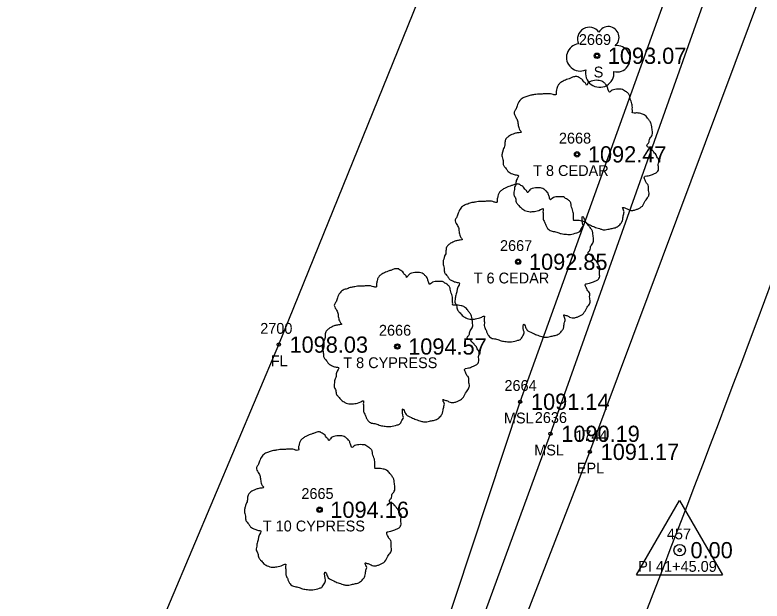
# Model space of a CAD drawing. Extents: x 1578957 to 1581675, y 1115963 to 1120391.
# Drawn here: x 1580656.7 to 1580725.7, y 1119311 to 1119365.2 of the extents above; entities that cross this region are included whole.
import ezdxf

# ---------------------------------------------------------------- set-up
doc = ezdxf.new("R2010")
doc.units = 0
for name, color, linetype in [('RD_EX_Fence_Other', 7, 'Continuous'), ('RD_EX_Fence_Other_txCode', 7, 'Continuous'), ('RD_EX_Misc', 7, 'Continuous'), ('RD_EX_Misc_txCode', 7, 'Continuous'), ('RD_EX_Road', 7, 'Continuous'), ('RD_EX_Road_txCode', 7, 'Continuous'), ('RD_EX_TX_Fence_Other_ELEV', 7, 'Continuous'), ('RD_EX_TX_Misc_ELEV', 7, 'Continuous'), ('RD_EX_TX_Road_ELEV', 7, 'Continuous'), ('RD_EX_TX_VEG_ELEV', 7, 'Continuous'), ('RD_EX_VEG', 7, 'Continuous'), ('RD_EX_VEG_txCode', 7, 'Continuous'), ('RD_HC_Cl', 7, 'Continuous'), ('RD_HC_Data', 7, 'Continuous'), ('RD_HC_Survey_ELEV', 7, 'Continuous'), ('RD_HC_txCode', 7, 'Continuous'), ('RD_SMD_Locator', 7, 'Continuous')]:
    doc.layers.add(name, color=color, linetype=linetype)

msp = doc.modelspace()

# ---------------------------------------------------------------- linework, layer by layer
at = {"layer": 'RD_EX_Fence_Other'}
msp.add_lwpolyline([(1580513.827, 1119078.662), (1580554.331, 1119026.263), (1580554.331, 1119026.263), (1580661.056, 1119287.238), (1580681.048, 1119334.68), (1580698.952, 1119378.888), (1580718.027, 1119424.961), (1580737.744, 1119473.232)], dxfattribs=at)
at = {"layer": 'RD_EX_Misc'}
for points in [[(1580575.469, 1119001.964), (1580572.192, 1119003.299), (1580573.344, 1119008.973), (1580569.078, 1119017.528), (1580583.69, 1119050.381), (1580599.817, 1119098.808), (1580624.045, 1119165.829), (1580641.396, 1119195.473), (1580666.371, 1119238.149), (1580687.021, 1119280.073), (1580703.349, 1119329.398), (1580719.477, 1119374.249), (1580736.36, 1119422.972), (1580751.158, 1119471.49)], [(1580572.228, 1119003.293), (1580577.641, 1119002.275), (1580593.887, 1119048.73), (1580611.465, 1119096.441), (1580629.396, 1119141.91), (1580650.31, 1119188.617), (1580669.532, 1119232.972), (1580689.078, 1119279.767), (1580706.148, 1119326.435), (1580722.862, 1119373.532), (1580740.07, 1119420.2), (1580755.304, 1119467.381)]]:
    msp.add_lwpolyline(points, dxfattribs=at)
at = {"layer": 'RD_EX_Road'}
msp.add_lwpolyline([(1580561.509, 1118902.856), (1580569.284, 1118952.033), (1580572.257, 1118964.729), (1580572.024, 1118971.684), (1580570.785, 1118976.943), (1580576.68, 1118999.159), (1580578.916, 1119000.71), (1580583.17, 1119008.339), (1580597.232, 1119047.928), (1580615.21, 1119094.659), (1580634.106, 1119140.594), (1580653.543, 1119186.411), (1580672.941, 1119232.27), (1580691.817, 1119278.399), (1580709.783, 1119324.767), (1580727.167, 1119371.358), (1580744.517, 1119418.33), (1580760.444, 1119465.683)], dxfattribs=at)
at = {"layer": 'RD_EX_VEG'}
for centre, radius in [((1580710.447, 1119361.381), 0.25), ((1580708.606, 1119352.268), 0.25), ((1580708.593, 1119352.249), 0.0001), ((1580703.165, 1119342.335), 0.25), ((1580703.152, 1119342.316), 0.0001), ((1580692.007, 1119334.506), 0.25), ((1580691.994, 1119334.487), 0.0001), ((1580684.82, 1119319.412), 0.25), ((1580684.807, 1119319.394), 0.0001)]:
    msp.add_circle(centre, radius, dxfattribs=at)
for centre, radius, start, end in [((1580709.726, 1119362.928), 1.084, 34.97629, 204.75602), ((1580711.492, 1119363.083), 0.995, 308.76261, 152.04674), ((1580708.883, 1119361.225), 1.257, 96.45179, 294.73401), ((1580712.287, 1119361.101), 1.218, 256.56668, 98.10463), ((1580710.692, 1119359.784), 1.318, 166.88266, 5.75893)]:
    msp.add_arc(centre, radius, start, end, dxfattribs=at)
for points in [[(1580708.738, 1119359.435), (1580708.438, 1119359.46), (1580708.113, 1119359.36), (1580707.863, 1119359.26), (1580707.638, 1119359.185), (1580707.413, 1119359.085), (1580707.113, 1119358.91), (1580706.888, 1119358.71), (1580706.763, 1119358.461), (1580706.713, 1119358.236), (1580706.663, 1119357.961), (1580706.663, 1119357.786), (1580706.539, 1119357.761), (1580706.389, 1119357.786), (1580706.139, 1119357.861), (1580705.889, 1119357.861), (1580705.639, 1119357.861), (1580705.289, 1119357.836), (1580704.939, 1119357.836), (1580704.664, 1119357.786), (1580704.339, 1119357.736), (1580703.965, 1119357.611), (1580703.615, 1119357.486), (1580703.315, 1119357.236), (1580703.065, 1119356.761), (1580702.94, 1119356.411), (1580702.79, 1119356.162), (1580702.94, 1119355.712), (1580703.115, 1119355.362), (1580703.14, 1119355.162), (1580703.215, 1119354.737), (1580703.315, 1119354.512), (1580703.44, 1119354.312), (1580703.365, 1119354.287), (1580702.99, 1119354.237), (1580702.69, 1119354.137), (1580702.265, 1119353.913), (1580702.04, 1119353.688), (1580701.94, 1119353.363), (1580701.916, 1119353.013), (1580701.816, 1119352.813), (1580701.741, 1119352.538), (1580701.716, 1119352.463), (1580701.666, 1119352.138), (1580701.766, 1119351.688), (1580701.791, 1119351.339), (1580701.916, 1119351.114), (1580702.065, 1119350.939), (1580702.24, 1119350.689), (1580702.64, 1119350.464), (1580702.965, 1119350.364), (1580703.165, 1119350.339), (1580702.99, 1119349.839), (1580702.94, 1119349.489), (1580702.815, 1119349.09), (1580702.815, 1119349.015), (1580702.765, 1119348.54), (1580702.915, 1119348.215), (1580702.99, 1119347.84), (1580703.165, 1119347.615), (1580703.44, 1119347.315), (1580703.765, 1119347.091), (1580704.265, 1119346.966), (1580704.664, 1119346.991), (1580705.239, 1119347.165), (1580705.489, 1119347.24), (1580705.464, 1119347.066), (1580705.489, 1119346.691), (1580705.489, 1119346.266), (1580705.639, 1119345.941), (1580705.739, 1119345.666), (1580705.889, 1119345.416), (1580706.214, 1119345.191), (1580706.613, 1119345.116), (1580707.038, 1119344.966), (1580707.488, 1119344.891), (1580707.988, 1119344.866), (1580708.588, 1119345.016), (1580708.862, 1119345.141), (1580708.962, 1119345.316), (1580709.162, 1119345.691), (1580709.112, 1119345.916), (1580709.137, 1119346.516), (1580709.237, 1119346.341), (1580709.412, 1119345.991), (1580709.912, 1119345.691), (1580710.312, 1119345.516), (1580710.787, 1119345.366), (1580711.087, 1119345.291), (1580711.561, 1119345.366), (1580711.936, 1119345.441), (1580712.311, 1119345.566), (1580712.611, 1119345.841), (1580712.786, 1119346.116), (1580712.836, 1119346.391), (1580712.911, 1119346.766), (1580712.961, 1119346.941)], [(1580712.961, 1119346.941), (1580712.886, 1119347.116), (1580712.836, 1119347.365), (1580712.911, 1119347.34), (1580713.086, 1119347.29), (1580713.361, 1119347.165), (1580713.585, 1119347.091), (1580713.91, 1119347.116), (1580714.185, 1119347.215), (1580714.635, 1119347.49), (1580714.91, 1119347.965), (1580715.185, 1119348.365), (1580715.26, 1119348.69), (1580715.21, 1119348.915), (1580715.185, 1119349.414), (1580714.985, 1119349.664), (1580714.935, 1119349.789), (1580714.835, 1119350.189), (1580714.91, 1119350.239), (1580715.185, 1119350.289), (1580715.56, 1119350.414), (1580715.834, 1119350.539), (1580716.059, 1119350.714), (1580716.134, 1119350.939), (1580716.109, 1119351.339), (1580716.159, 1119351.738), (1580716.084, 1119351.888), (1580715.984, 1119352.038), (1580715.909, 1119352.238), (1580715.759, 1119352.388), (1580715.66, 1119352.538), (1580715.56, 1119352.638), (1580715.435, 1119352.788), (1580715.26, 1119352.913), (1580715.11, 1119352.963), (1580715.06, 1119353.113), (1580715.21, 1119353.313), (1580715.26, 1119353.413), (1580715.285, 1119353.638), (1580715.51, 1119353.987), (1580715.56, 1119354.387), (1580715.51, 1119354.812), (1580715.46, 1119355.087), (1580715.31, 1119355.362), (1580715.11, 1119355.612), (1580714.985, 1119355.787), (1580714.81, 1119355.912), (1580714.485, 1119356.037), (1580714.235, 1119356.087), (1580713.885, 1119356.087), (1580713.685, 1119356.137), (1580713.71, 1119356.187), (1580713.71, 1119356.336), (1580713.71, 1119356.611), (1580713.635, 1119357.061), (1580713.485, 1119357.561), (1580713.485, 1119357.586), (1580713.385, 1119357.836), (1580713.161, 1119358.036), (1580712.986, 1119358.136), (1580712.786, 1119358.261), (1580712.536, 1119358.286), (1580712.236, 1119358.286), (1580711.961, 1119358.236), (1580711.761, 1119358.136), (1580711.586, 1119358.011), (1580711.511, 1119358.161), (1580711.411, 1119358.461), (1580711.361, 1119358.61), (1580711.211, 1119358.785), (1580710.987, 1119358.985), (1580710.537, 1119359.11), (1580709.912, 1119359.035), (1580709.612, 1119358.835), (1580709.462, 1119358.66), (1580709.412, 1119358.785), (1580709.212, 1119358.985), (1580709.112, 1119359.16), (1580708.937, 1119359.285), (1580708.788, 1119359.385), (1580708.688, 1119359.435)], [(1580703.297, 1119349.502), (1580702.997, 1119349.527), (1580702.672, 1119349.427), (1580702.422, 1119349.327), (1580702.197, 1119349.252), (1580701.972, 1119349.152), (1580701.673, 1119348.977), (1580701.448, 1119348.777), (1580701.323, 1119348.527), (1580701.273, 1119348.302), (1580701.223, 1119348.028), (1580701.223, 1119347.853), (1580701.098, 1119347.828), (1580700.948, 1119347.853), (1580700.698, 1119347.928), (1580700.448, 1119347.928), (1580700.198, 1119347.928), (1580699.848, 1119347.903), (1580699.498, 1119347.903), (1580699.224, 1119347.853), (1580698.899, 1119347.803), (1580698.524, 1119347.678), (1580698.174, 1119347.553), (1580697.874, 1119347.303), (1580697.624, 1119346.828), (1580697.499, 1119346.478), (1580697.349, 1119346.228), (1580697.499, 1119345.779), (1580697.674, 1119345.429), (1580697.699, 1119345.229), (1580697.774, 1119344.804), (1580697.874, 1119344.579), (1580697.999, 1119344.379), (1580697.924, 1119344.354), (1580697.549, 1119344.304), (1580697.249, 1119344.204), (1580696.825, 1119343.979), (1580696.6, 1119343.754), (1580696.5, 1119343.429), (1580696.475, 1119343.08), (1580696.375, 1119342.88), (1580696.3, 1119342.605), (1580696.275, 1119342.53), (1580696.225, 1119342.205), (1580696.325, 1119341.755), (1580696.35, 1119341.405), (1580696.475, 1119341.18), (1580696.625, 1119341.006), (1580696.8, 1119340.756), (1580697.199, 1119340.531), (1580697.524, 1119340.431), (1580697.724, 1119340.406), (1580697.549, 1119339.906), (1580697.499, 1119339.556), (1580697.374, 1119339.156), (1580697.374, 1119339.081), (1580697.324, 1119338.607), (1580697.474, 1119338.282), (1580697.549, 1119337.907), (1580697.724, 1119337.682), (1580697.999, 1119337.382), (1580698.324, 1119337.157), (1580698.824, 1119337.032), (1580699.224, 1119337.057), (1580699.798, 1119337.232), (1580700.048, 1119337.307), (1580700.023, 1119337.132), (1580700.048, 1119336.757), (1580700.048, 1119336.333), (1580700.198, 1119336.008), (1580700.298, 1119335.733), (1580700.448, 1119335.483), (1580700.773, 1119335.258), (1580701.173, 1119335.183), (1580701.598, 1119335.033), (1580702.047, 1119334.958), (1580702.547, 1119334.933), (1580703.147, 1119335.083), (1580703.422, 1119335.208), (1580703.522, 1119335.383), (1580703.722, 1119335.758), (1580703.672, 1119335.983), (1580703.697, 1119336.583), (1580703.797, 1119336.408), (1580703.972, 1119336.058), (1580704.471, 1119335.758), (1580704.871, 1119335.583), (1580705.346, 1119335.433), (1580705.646, 1119335.358), (1580706.121, 1119335.433), (1580706.495, 1119335.508), (1580706.87, 1119335.633), (1580707.17, 1119335.908), (1580707.345, 1119336.183), (1580707.395, 1119336.458), (1580707.47, 1119336.832), (1580707.52, 1119337.007)], [(1580707.52, 1119337.007), (1580707.445, 1119337.182), (1580707.395, 1119337.432), (1580707.47, 1119337.407), (1580707.645, 1119337.357), (1580707.92, 1119337.232), (1580708.145, 1119337.157), (1580708.47, 1119337.182), (1580708.744, 1119337.282), (1580709.194, 1119337.557), (1580709.469, 1119338.032), (1580709.744, 1119338.432), (1580709.819, 1119338.757), (1580709.769, 1119338.981), (1580709.744, 1119339.481), (1580709.544, 1119339.731), (1580709.494, 1119339.856), (1580709.394, 1119340.256), (1580709.469, 1119340.306), (1580709.744, 1119340.356), (1580710.119, 1119340.481), (1580710.394, 1119340.606), (1580710.619, 1119340.781), (1580710.694, 1119341.006), (1580710.669, 1119341.405), (1580710.719, 1119341.805), (1580710.644, 1119341.955), (1580710.544, 1119342.105), (1580710.469, 1119342.305), (1580710.319, 1119342.455), (1580710.219, 1119342.605), (1580710.119, 1119342.705), (1580709.994, 1119342.855), (1580709.819, 1119342.98), (1580709.669, 1119343.03), (1580709.619, 1119343.18), (1580709.769, 1119343.38), (1580709.819, 1119343.479), (1580709.844, 1119343.704), (1580710.069, 1119344.054), (1580710.119, 1119344.454), (1580710.069, 1119344.879), (1580710.019, 1119345.154), (1580709.869, 1119345.429), (1580709.669, 1119345.679), (1580709.544, 1119345.853), (1580709.369, 1119345.978), (1580709.044, 1119346.103), (1580708.794, 1119346.153), (1580708.445, 1119346.153), (1580708.245, 1119346.203), (1580708.27, 1119346.253), (1580708.27, 1119346.403), (1580708.27, 1119346.678), (1580708.195, 1119347.128), (1580708.045, 1119347.628), (1580708.045, 1119347.653), (1580707.945, 1119347.903), (1580707.72, 1119348.102), (1580707.545, 1119348.202), (1580707.345, 1119348.327), (1580707.095, 1119348.352), (1580706.795, 1119348.352), (1580706.52, 1119348.302), (1580706.32, 1119348.202), (1580706.146, 1119348.077), (1580706.071, 1119348.227), (1580705.971, 1119348.527), (1580705.921, 1119348.677), (1580705.771, 1119348.852), (1580705.546, 1119349.052), (1580705.096, 1119349.177), (1580704.471, 1119349.102), (1580704.171, 1119348.902), (1580704.021, 1119348.727), (1580703.972, 1119348.852), (1580703.772, 1119349.052), (1580703.672, 1119349.227), (1580703.497, 1119349.352), (1580703.347, 1119349.452), (1580703.247, 1119349.502)], [(1580692.139, 1119341.673), (1580691.839, 1119341.698), (1580691.514, 1119341.598), (1580691.264, 1119341.498), (1580691.039, 1119341.423), (1580690.814, 1119341.323), (1580690.514, 1119341.149), (1580690.29, 1119340.949), (1580690.165, 1119340.699), (1580690.115, 1119340.474), (1580690.065, 1119340.199), (1580690.065, 1119340.024), (1580689.94, 1119339.999), (1580689.79, 1119340.024), (1580689.54, 1119340.099), (1580689.29, 1119340.099), (1580689.04, 1119340.099), (1580688.69, 1119340.074), (1580688.34, 1119340.074), (1580688.066, 1119340.024), (1580687.741, 1119339.974), (1580687.366, 1119339.849), (1580687.016, 1119339.724), (1580686.716, 1119339.474), (1580686.466, 1119339), (1580686.341, 1119338.65), (1580686.191, 1119338.4), (1580686.341, 1119337.95), (1580686.516, 1119337.6), (1580686.541, 1119337.4), (1580686.616, 1119336.975), (1580686.716, 1119336.751), (1580686.841, 1119336.551), (1580686.766, 1119336.526), (1580686.391, 1119336.476), (1580686.091, 1119336.376), (1580685.667, 1119336.151), (1580685.442, 1119335.926), (1580685.342, 1119335.601), (1580685.317, 1119335.251), (1580685.217, 1119335.051), (1580685.142, 1119334.776), (1580685.117, 1119334.701), (1580685.067, 1119334.377), (1580685.167, 1119333.927), (1580685.192, 1119333.577), (1580685.317, 1119333.352), (1580685.467, 1119333.177), (1580685.642, 1119332.927), (1580686.041, 1119332.702), (1580686.366, 1119332.602), (1580686.566, 1119332.577), (1580686.391, 1119332.078), (1580686.341, 1119331.728), (1580686.216, 1119331.328), (1580686.216, 1119331.253), (1580686.166, 1119330.778), (1580686.316, 1119330.453), (1580686.391, 1119330.078), (1580686.566, 1119329.854), (1580686.841, 1119329.554), (1580687.166, 1119329.329), (1580687.666, 1119329.204), (1580688.066, 1119329.229), (1580688.64, 1119329.404), (1580688.89, 1119329.479), (1580688.865, 1119329.304), (1580688.89, 1119328.929), (1580688.89, 1119328.504), (1580689.04, 1119328.179), (1580689.14, 1119327.904), (1580689.29, 1119327.654), (1580689.615, 1119327.43), (1580690.015, 1119327.355), (1580690.439, 1119327.205), (1580690.889, 1119327.13), (1580691.389, 1119327.105), (1580691.989, 1119327.255), (1580692.264, 1119327.38), (1580692.364, 1119327.555), (1580692.564, 1119327.929), (1580692.514, 1119328.154), (1580692.539, 1119328.754), (1580692.638, 1119328.579), (1580692.813, 1119328.229), (1580693.313, 1119327.929), (1580693.713, 1119327.754), (1580694.188, 1119327.604), (1580694.488, 1119327.53), (1580694.962, 1119327.604), (1580695.337, 1119327.679), (1580695.712, 1119327.804), (1580696.012, 1119328.079), (1580696.187, 1119328.354), (1580696.237, 1119328.629), (1580696.312, 1119329.004), (1580696.362, 1119329.179)], [(1580696.362, 1119329.179), (1580696.287, 1119329.354), (1580696.237, 1119329.604), (1580696.312, 1119329.579), (1580696.487, 1119329.529), (1580696.762, 1119329.404), (1580696.987, 1119329.329), (1580697.311, 1119329.354), (1580697.586, 1119329.454), (1580698.036, 1119329.729), (1580698.311, 1119330.203), (1580698.586, 1119330.603), (1580698.661, 1119330.928), (1580698.611, 1119331.153), (1580698.586, 1119331.653), (1580698.386, 1119331.903), (1580698.336, 1119332.028), (1580698.236, 1119332.427), (1580698.311, 1119332.477), (1580698.586, 1119332.527), (1580698.961, 1119332.652), (1580699.236, 1119332.777), (1580699.461, 1119332.952), (1580699.535, 1119333.177), (1580699.511, 1119333.577), (1580699.56, 1119333.977), (1580699.486, 1119334.127), (1580699.386, 1119334.277), (1580699.311, 1119334.477), (1580699.161, 1119334.626), (1580699.061, 1119334.776), (1580698.961, 1119334.876), (1580698.836, 1119335.026), (1580698.661, 1119335.151), (1580698.511, 1119335.201), (1580698.461, 1119335.351), (1580698.611, 1119335.551), (1580698.661, 1119335.651), (1580698.686, 1119335.876), (1580698.911, 1119336.226), (1580698.961, 1119336.626), (1580698.911, 1119337.05), (1580698.861, 1119337.325), (1580698.711, 1119337.6), (1580698.511, 1119337.85), (1580698.386, 1119338.025), (1580698.211, 1119338.15), (1580697.886, 1119338.275), (1580697.636, 1119338.325), (1580697.286, 1119338.325), (1580697.087, 1119338.375), (1580697.112, 1119338.425), (1580697.112, 1119338.575), (1580697.112, 1119338.85), (1580697.037, 1119339.299), (1580696.887, 1119339.799), (1580696.887, 1119339.824), (1580696.787, 1119340.074), (1580696.562, 1119340.274), (1580696.387, 1119340.374), (1580696.187, 1119340.499), (1580695.937, 1119340.524), (1580695.637, 1119340.524), (1580695.362, 1119340.474), (1580695.162, 1119340.374), (1580694.987, 1119340.249), (1580694.912, 1119340.399), (1580694.813, 1119340.699), (1580694.763, 1119340.849), (1580694.613, 1119341.024), (1580694.388, 1119341.224), (1580693.938, 1119341.348), (1580693.313, 1119341.274), (1580693.013, 1119341.074), (1580692.863, 1119340.899), (1580692.813, 1119341.024), (1580692.613, 1119341.224), (1580692.514, 1119341.398), (1580692.339, 1119341.523), (1580692.189, 1119341.623), (1580692.089, 1119341.673)], [(1580684.952, 1119326.58), (1580684.652, 1119326.605), (1580684.327, 1119326.505), (1580684.077, 1119326.405), (1580683.852, 1119326.33), (1580683.627, 1119326.23), (1580683.327, 1119326.055), (1580683.102, 1119325.855), (1580682.977, 1119325.605), (1580682.927, 1119325.38), (1580682.877, 1119325.105), (1580682.877, 1119324.93), (1580682.753, 1119324.905), (1580682.603, 1119324.93), (1580682.353, 1119325.005), (1580682.103, 1119325.005), (1580681.853, 1119325.005), (1580681.503, 1119324.98), (1580681.153, 1119324.98), (1580680.878, 1119324.93), (1580680.553, 1119324.88), (1580680.179, 1119324.755), (1580679.829, 1119324.63), (1580679.529, 1119324.381), (1580679.279, 1119323.906), (1580679.154, 1119323.556), (1580679.004, 1119323.306), (1580679.154, 1119322.856), (1580679.329, 1119322.506), (1580679.354, 1119322.306), (1580679.429, 1119321.882), (1580679.529, 1119321.657), (1580679.654, 1119321.457), (1580679.579, 1119321.432), (1580679.204, 1119321.382), (1580678.904, 1119321.282), (1580678.479, 1119321.057), (1580678.254, 1119320.832), (1580678.154, 1119320.507), (1580678.13, 1119320.157), (1580678.03, 1119319.958), (1580677.955, 1119319.683), (1580677.93, 1119319.608), (1580677.88, 1119319.283), (1580677.98, 1119318.833), (1580678.005, 1119318.483), (1580678.13, 1119318.258), (1580678.279, 1119318.083), (1580678.454, 1119317.833), (1580678.854, 1119317.609), (1580679.179, 1119317.509), (1580679.379, 1119317.484), (1580679.204, 1119316.984), (1580679.154, 1119316.634), (1580679.029, 1119316.234), (1580679.029, 1119316.159), (1580678.979, 1119315.684), (1580679.129, 1119315.359), (1580679.204, 1119314.985), (1580679.379, 1119314.76), (1580679.654, 1119314.46), (1580679.979, 1119314.235), (1580680.479, 1119314.11), (1580680.878, 1119314.135), (1580681.453, 1119314.31), (1580681.703, 1119314.385), (1580681.678, 1119314.21), (1580681.703, 1119313.835), (1580681.703, 1119313.41), (1580681.853, 1119313.086), (1580681.953, 1119312.811), (1580682.103, 1119312.561), (1580682.428, 1119312.336), (1580682.827, 1119312.261), (1580683.252, 1119312.111), (1580683.702, 1119312.036), (1580684.202, 1119312.011), (1580684.802, 1119312.161), (1580685.076, 1119312.286), (1580685.176, 1119312.461), (1580685.376, 1119312.836), (1580685.326, 1119313.061), (1580685.351, 1119313.66), (1580685.451, 1119313.485), (1580685.626, 1119313.135), (1580686.126, 1119312.836), (1580686.526, 1119312.661), (1580687.001, 1119312.511), (1580687.301, 1119312.436), (1580687.775, 1119312.511), (1580688.15, 1119312.586), (1580688.525, 1119312.711), (1580688.825, 1119312.986), (1580689, 1119313.26), (1580689.05, 1119313.535), (1580689.125, 1119313.91), (1580689.175, 1119314.085)], [(1580689.175, 1119314.085), (1580689.1, 1119314.26), (1580689.05, 1119314.51), (1580689.125, 1119314.485), (1580689.3, 1119314.435), (1580689.575, 1119314.31), (1580689.799, 1119314.235), (1580690.124, 1119314.26), (1580690.399, 1119314.36), (1580690.849, 1119314.635), (1580691.124, 1119315.11), (1580691.399, 1119315.509), (1580691.474, 1119315.834), (1580691.424, 1119316.059), (1580691.399, 1119316.559), (1580691.199, 1119316.809), (1580691.149, 1119316.934), (1580691.049, 1119317.334), (1580691.124, 1119317.384), (1580691.399, 1119317.434), (1580691.774, 1119317.559), (1580692.048, 1119317.683), (1580692.273, 1119317.858), (1580692.348, 1119318.083), (1580692.323, 1119318.483), (1580692.373, 1119318.883), (1580692.298, 1119319.033), (1580692.198, 1119319.183), (1580692.123, 1119319.383), (1580691.973, 1119319.533), (1580691.874, 1119319.683), (1580691.774, 1119319.783), (1580691.649, 1119319.933), (1580691.474, 1119320.057), (1580691.324, 1119320.107), (1580691.274, 1119320.257), (1580691.424, 1119320.457), (1580691.474, 1119320.557), (1580691.499, 1119320.782), (1580691.724, 1119321.132), (1580691.774, 1119321.532), (1580691.724, 1119321.957), (1580691.674, 1119322.232), (1580691.524, 1119322.506), (1580691.324, 1119322.756), (1580691.199, 1119322.931), (1580691.024, 1119323.056), (1580690.699, 1119323.181), (1580690.449, 1119323.231), (1580690.099, 1119323.231), (1580689.899, 1119323.281), (1580689.924, 1119323.331), (1580689.924, 1119323.481), (1580689.924, 1119323.756), (1580689.849, 1119324.206), (1580689.699, 1119324.705), (1580689.699, 1119324.73), (1580689.599, 1119324.98), (1580689.375, 1119325.18), (1580689.2, 1119325.28), (1580689, 1119325.405), (1580688.75, 1119325.43), (1580688.45, 1119325.43), (1580688.175, 1119325.38), (1580687.975, 1119325.28), (1580687.8, 1119325.155), (1580687.725, 1119325.305), (1580687.625, 1119325.605), (1580687.575, 1119325.755), (1580687.425, 1119325.93), (1580687.201, 1119326.13), (1580686.751, 1119326.255), (1580686.126, 1119326.18), (1580685.826, 1119325.98), (1580685.676, 1119325.805), (1580685.626, 1119325.93), (1580685.426, 1119326.13), (1580685.326, 1119326.305), (1580685.151, 1119326.43), (1580685.002, 1119326.53), (1580684.902, 1119326.58)]]:
    msp.add_spline(points, degree=3, dxfattribs=at)
at = {"layer": 'RD_HC_Cl'}
msp.add_arc((1578340.815, 1120231.591), 2546.774, 337.467285, 340.391325, dxfattribs=at)
at = {"layer": 'RD_HC_Data'}
for p, q in [((1580714.108, 1119313.385), (1580718.08, 1119320.265)), ((1580718.08, 1119320.265), (1580722.049, 1119313.385)), ((1580714.108, 1119313.385), (1580722.049, 1119313.385))]:
    msp.add_line(p, q, dxfattribs=at)
msp.add_circle((1580718.079, 1119315.678), 0.529, dxfattribs=at)
at = {"layer": 'RD_SMD_Locator'}
for centre in [(1580710.447, 1119361.381), (1580708.606, 1119352.268), (1580703.165, 1119342.335), (1580681.048, 1119334.68), (1580692.007, 1119334.506), (1580703.349, 1119329.398), (1580706.148, 1119326.435), (1580709.783, 1119324.767), (1580684.82, 1119319.412), (1580718.079, 1119315.678)]:
    msp.add_circle(centre, 0.15, dxfattribs=at)

# ---------------------------------------------------------------- texts
at = {"layer": 'RD_EX_Fence_Other_txCode'}
for s, p in [('2700', (1580679.339, 1119335.68)), ('FL', (1580680.316, 1119332.68))]:
    msp.add_text(s, height=1, dxfattribs=at).set_placement(p)
at = {"layer": 'RD_EX_Misc_txCode'}
for s, p in [('2664', (1580701.897, 1119330.398)), ('MSL', (1580701.847, 1119327.398)), ('2636', (1580704.699, 1119327.435)), ('MSL', (1580704.646, 1119324.435))]:
    msp.add_text(s, height=1, dxfattribs=at).set_placement(p)
at = {"layer": 'RD_EX_Road_txCode'}
for s, p in [('1744', (1580708.437, 1119325.767)), ('EPL', (1580708.578, 1119322.767))]:
    msp.add_text(s, height=1, dxfattribs=at).set_placement(p)
at = {"layer": 'RD_EX_TX_Fence_Other_ELEV'}
msp.add_text('1098.03', height=1.5, dxfattribs=at).set_placement((1580682.048, 1119333.93))
at = {"layer": 'RD_EX_TX_Misc_ELEV'}
for s, p in [('1091.14', (1580704.349, 1119328.648)), ('1090.19', (1580707.148, 1119325.685))]:
    msp.add_text(s, height=1.5, dxfattribs=at).set_placement(p)
at = {"layer": 'RD_EX_TX_Road_ELEV'}
msp.add_text('1091.17', height=1.5, dxfattribs=at).set_placement((1580710.783, 1119324.017))
at = {"layer": 'RD_EX_TX_VEG_ELEV'}
for s, p in [('1093.07', (1580711.447, 1119360.631)), ('1092.47', (1580709.606, 1119351.518)), ('1092.85', (1580704.165, 1119341.585)), ('1094.57', (1580693.007, 1119333.756)), ('1094.16', (1580685.82, 1119318.662))]:
    msp.add_text(s, height=1.5, dxfattribs=at).set_placement(p)
at = {"layer": 'RD_EX_VEG_txCode'}
for s, p in [('2669', (1580708.77, 1119362.381)), ('S', (1580710.14, 1119359.381)), ('2668', (1580706.928, 1119353.268)), ('T 8 CEDAR', (1580704.543, 1119350.268)), ('2667', (1580701.488, 1119343.335)), ('T 6 CEDAR', (1580699.055, 1119340.335)), ('2666', (1580690.306, 1119335.506)), ('T 8 CYPRESS', (1580687.007, 1119332.506)), ('2665', (1580683.142, 1119320.412)), ('T 10 CYPRESS', (1580679.576, 1119317.412))]:
    msp.add_text(s, height=1, dxfattribs=at).set_placement(p)
at = {"layer": 'RD_HC_Survey_ELEV'}
msp.add_text('0.00', height=1.5, dxfattribs=at).set_placement((1580719.079, 1119314.928))
at = {"layer": 'RD_HC_txCode'}
for s, p in [('457', (1580716.897, 1119316.678)), ('PI 41+45.09', (1580714.26, 1119313.678))]:
    msp.add_text(s, height=1, dxfattribs=at).set_placement(p)

doc.saveas('drawing.dxf')
